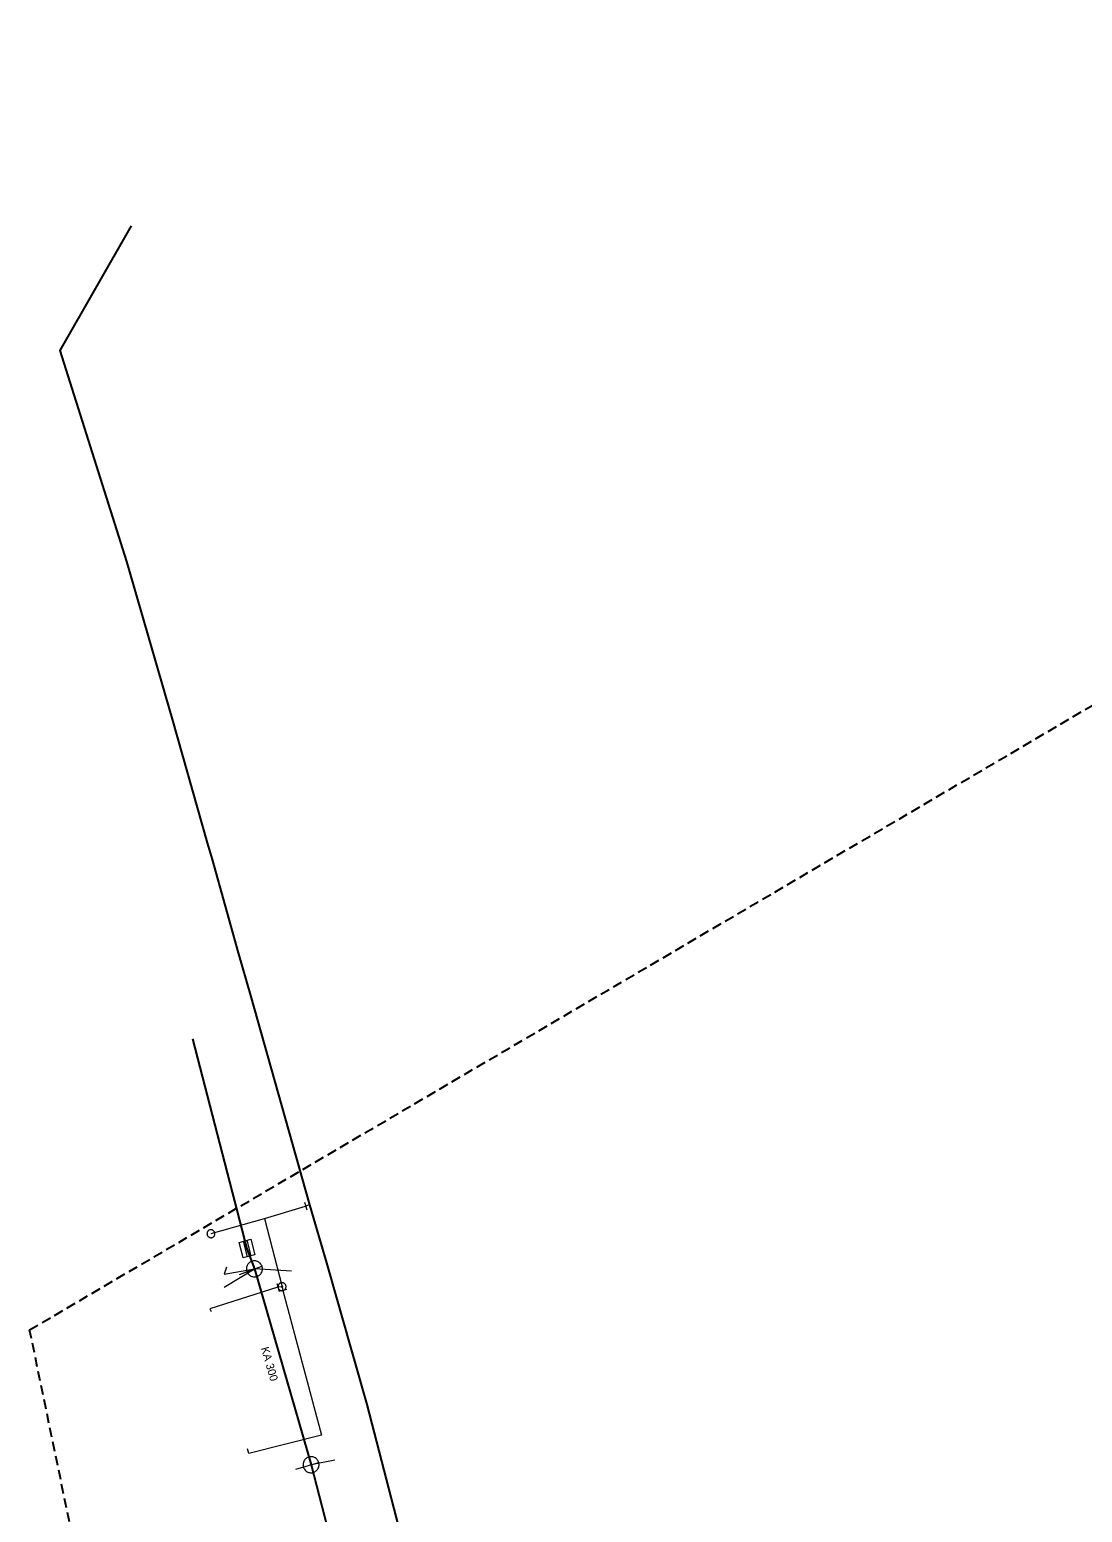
# Model space of a CAD drawing. Extents: x -807203 to -805207, y -993656 to -992505.
# Drawn here: x -807189 to -807057.5, y -992968.6 to -992783.3 of the extents above; entities that cross this region are included whole.
import ezdxf

# ---------------------------------------------------------------- set-up
doc = ezdxf.new("R2010")
doc.units = 0
doc.header["$LTSCALE"] = 0.4
doc.linetypes.add('MEDIUM_DASHED', pattern=[4.5, 3, -1.5])
for name, color, linetype, lineweight in [('1', 7, 'Continuous', 13), ('11', 7, 'Continuous', 13), ('13', 7, 'Continuous', 13), ('14', 7, 'Continuous', 25), ('17', 7, 'Continuous', 25), ('22', 7, 'Continuous', 13), ('23', 7, 'Continuous', 13), ('34', 7, 'Continuous', 13), ('47', 7, 'Continuous', 13), ('63', 7, 'MEDIUM_DASHED', 25)]:
    doc.layers.add(name, color=color, linetype=linetype, lineweight=lineweight)

msp = doc.modelspace()

# ---------------------------------------------------------------- linework, layer by layer
at = {"layer": '11'}
for p, q in [((-807164.698, -992940.463), (-807160.93, -992938.18)), ((-807156.287, -992938.489), (-807160.93, -992938.18)), ((-807150.881, -992962.09), (-807153.859, -992962.66))]:
    msp.add_line(p, q, dxfattribs=at)
msp.add_lwpolyline([(-807164.44, -992937.974), (-807164.698, -992938.833), (-807160.93, -992938.18)], dxfattribs=at)
at = {"layer": '13'}
for p, q in [((-807154.07, -992930.199), (-807154.533, -992930.34)), ((-807159.671, -992931.895), (-807157.484, -992940.411))]:
    msp.add_line(p, q, dxfattribs=at)
for points in [[(-807166.339, -992933.77), (-807159.671, -992931.895), (-807154.533, -992930.34)], [(-807157.996, -992940.48), (-807166.495, -992943.176), (-807166.358, -992943.517)], [(-807157.381, -992940.889), (-807152.535, -992958.945), (-807161.614, -992961.266), (-807161.819, -992960.686)]]:
    msp.add_lwpolyline(points, dxfattribs=at)
at = {"layer": '14'}
for p, q in [((-807168.67, -992909.44), (-807161.87, -992935.66)), ((-807161.87, -992935.66), (-807160.93, -992938.18)), ((-807160.93, -992938.18), (-807153.859, -992962.66)), ((-807153.859, -992962.66), (-807147.12, -992988.77))]:
    msp.add_line(p, q, dxfattribs=at)
at = {"layer": '14', "lineweight": 13}
for q in [(-807157.996, -992940.48), (-807157.381, -992940.889)]:
    msp.add_line((-807157.484, -992940.411), q, dxfattribs=at)
at = {"layer": '17'}
msp.add_lwpolyline([(-807176.339, -992807.832), (-807185.25, -992823.421), (-807176.901, -992849.778), (-807171.201, -992869.482), (-807166.822, -992884.952), (-807166.197, -992887.01), (-807162.951, -992898.684), (-807161.445, -992904.008), (-807154.07, -992930.199), (-807151.949, -992937.442), (-807146.899, -992955.136), (-807141.44, -992976.222)], dxfattribs=at)
at = {"layer": '22'}
for p, q in [((-807162.359, -992934.742), (-807161.857, -992936.678)), ((-807161.875, -992934.616), (-807161.373, -992936.552)), ((-807162.804, -992938.879), (-807159.993, -992937.83)), ((-807155.78, -992963.215), (-807152.898, -992962.382))]:
    msp.add_line(p, q, dxfattribs=at)
for points in [[(-807161.391, -992934.491), (-807160.889, -992936.427), (-807162.341, -992936.803), (-807162.843, -992934.868)], [(-807160.58, -992939.117), (-807160.48, -992939.073), (-807160.386, -992939.018), (-807160.297, -992938.953), (-807160.216, -992938.88), (-807160.143, -992938.798), (-807160.081, -992938.708), (-807160.028, -992938.612), (-807159.987, -992938.511), (-807159.956, -992938.405), (-807159.937, -992938.298), (-807159.93, -992938.189), (-807159.936, -992938.079), (-807159.952, -992937.971), (-807159.981, -992937.865), (-807160.021, -992937.763), (-807160.072, -992937.667), (-807160.133, -992937.575), (-807160.204, -992937.491), (-807160.284, -992937.417), (-807160.37, -992937.351), (-807160.465, -992937.294), (-807160.564, -992937.249), (-807160.669, -992937.215), (-807160.776, -992937.191), (-807160.884, -992937.181), (-807160.994, -992937.182), (-807161.103, -992937.195), (-807161.209, -992937.22), (-807161.313, -992937.256), (-807161.411, -992937.304), (-807161.504, -992937.361), (-807161.59, -992937.429), (-807161.668, -992937.505), (-807161.738, -992937.59), (-807161.797, -992937.682), (-807161.847, -992937.78), (-807161.885, -992937.883), (-807161.912, -992937.989), (-807161.927, -992938.097), (-807161.93, -992938.207), (-807161.921, -992938.316), (-807161.9, -992938.423), (-807161.867, -992938.528), (-807161.824, -992938.628), (-807161.769, -992938.723), (-807161.705, -992938.811), (-807161.631, -992938.893), (-807161.548, -992938.965), (-807161.459, -992939.028), (-807161.363, -992939.081), (-807161.262, -992939.123), (-807161.157, -992939.153), (-807161.049, -992939.173), (-807160.94, -992939.179), (-807160.831, -992939.175), (-807160.722, -992939.158), (-807160.616, -992939.129)], [(-807153.582, -992963.62), (-807153.478, -992963.584), (-807153.38, -992963.537), (-807153.286, -992963.479), (-807153.2, -992963.412), (-807153.121, -992963.336), (-807153.052, -992963.251), (-807152.992, -992963.159), (-807152.944, -992963.061), (-807152.905, -992962.959), (-807152.878, -992962.853), (-807152.862, -992962.744), (-807152.86, -992962.634), (-807152.868, -992962.525), (-807152.889, -992962.418), (-807152.921, -992962.313), (-807152.965, -992962.213), (-807153.019, -992962.117), (-807153.083, -992962.028), (-807153.157, -992961.948), (-807153.238, -992961.876), (-807153.328, -992961.812), (-807153.424, -992961.76), (-807153.525, -992961.717), (-807153.63, -992961.686), (-807153.738, -992961.667), (-807153.847, -992961.66), (-807153.957, -992961.665), (-807154.065, -992961.681), (-807154.171, -992961.71), (-807154.273, -992961.75), (-807154.37, -992961.8), (-807154.46, -992961.861), (-807154.544, -992961.931), (-807154.62, -992962.01), (-807154.686, -992962.098), (-807154.743, -992962.191), (-807154.789, -992962.291), (-807154.823, -992962.395), (-807154.847, -992962.501), (-807154.858, -992962.611), (-807154.857, -992962.72), (-807154.845, -992962.829), (-807154.82, -992962.936), (-807154.784, -992963.039), (-807154.737, -992963.138), (-807154.68, -992963.231), (-807154.612, -992963.317), (-807154.535, -992963.396), (-807154.451, -992963.465), (-807154.359, -992963.525), (-807154.262, -992963.575), (-807154.159, -992963.613), (-807154.053, -992963.641), (-807153.945, -992963.656), (-807153.836, -992963.659), (-807153.726, -992963.651), (-807153.618, -992963.63)]]:
    msp.add_lwpolyline(points, close=True, dxfattribs=at)
at = {"layer": '23'}
for points in [[(-807165.862, -992933.787), (-807165.865, -992933.734), (-807165.874, -992933.682), (-807165.889, -992933.633), (-807165.908, -992933.584), (-807165.932, -992933.538), (-807165.962, -992933.494), (-807165.995, -992933.454), (-807166.032, -992933.418), (-807166.073, -992933.385), (-807166.117, -992933.357), (-807166.164, -992933.333), (-807166.214, -992933.315), (-807166.264, -992933.302), (-807166.315, -992933.295), (-807166.367, -992933.292), (-807166.421, -992933.296), (-807166.471, -992933.304), (-807166.523, -992933.319), (-807166.57, -992933.337), (-807166.617, -992933.361), (-807166.661, -992933.392), (-807166.701, -992933.425), (-807166.738, -992933.463), (-807166.771, -992933.503), (-807166.798, -992933.547), (-807166.821, -992933.595), (-807166.839, -992933.643), (-807166.852, -992933.694), (-807166.859, -992933.746), (-807166.862, -992933.798), (-807166.859, -992933.85), (-807166.85, -992933.902), (-807166.836, -992933.953), (-807166.817, -992934.001), (-807166.792, -992934.046), (-807166.763, -992934.09), (-807166.73, -992934.131), (-807166.692, -992934.168), (-807166.651, -992934.2)], [(-807166.523, -992933.319), (-807166.57, -992933.337), (-807166.617, -992933.361), (-807166.661, -992933.392), (-807166.701, -992933.425), (-807166.738, -992933.463), (-807166.771, -992933.503), (-807166.798, -992933.547), (-807166.821, -992933.595), (-807166.839, -992933.643), (-807166.852, -992933.694), (-807166.859, -992933.746), (-807166.862, -992933.798), (-807166.859, -992933.85), (-807166.85, -992933.902), (-807166.836, -992933.953), (-807166.817, -992934.001), (-807166.792, -992934.046), (-807166.763, -992934.09), (-807166.73, -992934.131), (-807166.692, -992934.168), (-807166.651, -992934.2), (-807166.608, -992934.228), (-807166.56, -992934.251), (-807166.512, -992934.27), (-807166.46, -992934.282), (-807166.409, -992934.289), (-807166.357, -992934.292), (-807166.305, -992934.288), (-807166.253, -992934.28), (-807166.202, -992934.266), (-807166.154, -992934.246), (-807166.107, -992934.222), (-807166.064, -992934.194), (-807166.024, -992934.159), (-807165.987, -992934.123), (-807165.955, -992934.082), (-807165.926, -992934.037), (-807165.903, -992933.99), (-807165.885, -992933.941)], [(-807166.651, -992934.2), (-807166.608, -992934.228), (-807166.56, -992934.251), (-807166.512, -992934.27), (-807166.46, -992934.282), (-807166.409, -992934.289), (-807166.357, -992934.292), (-807166.305, -992934.288), (-807166.253, -992934.28), (-807166.202, -992934.266), (-807166.154, -992934.246), (-807166.107, -992934.222), (-807166.064, -992934.194), (-807166.024, -992934.159), (-807165.987, -992934.123), (-807165.955, -992934.082), (-807165.926, -992934.037), (-807165.903, -992933.99), (-807165.885, -992933.941), (-807165.873, -992933.89), (-807165.865, -992933.839), (-807165.862, -992933.787), (-807165.865, -992933.734), (-807165.874, -992933.682), (-807165.889, -992933.633), (-807165.908, -992933.584), (-807165.932, -992933.538), (-807165.962, -992933.494), (-807165.995, -992933.454), (-807166.032, -992933.418), (-807166.073, -992933.385), (-807166.117, -992933.357), (-807166.164, -992933.333), (-807166.214, -992933.315), (-807166.264, -992933.302), (-807166.315, -992933.295), (-807166.367, -992933.292), (-807166.421, -992933.296), (-807166.471, -992933.304), (-807166.523, -992933.319)], [(-807165.885, -992933.941), (-807165.873, -992933.89), (-807165.865, -992933.839), (-807165.862, -992933.787)]]:
    msp.add_lwpolyline(points, dxfattribs=at)
at = {"layer": '34'}
for p, q in [((-807154.678, -992929.861), (-807154.388, -992930.818)), ((-807158.136, -992940), (-807157.856, -992940.96)), ((-807156.896, -992940.765), (-807157.865, -992941.011))]:
    msp.add_line(p, q, dxfattribs=at)
at = {"layer": '47'}
for points in [[(-807157.359, -992940.895), (-807157.31, -992940.879), (-807157.261, -992940.858), (-807157.216, -992940.832), (-807157.173, -992940.803), (-807157.134, -992940.768), (-807157.098, -992940.729), (-807157.068, -992940.687), (-807157.041, -992940.642), (-807157.019, -992940.595), (-807157.002, -992940.545), (-807156.99, -992940.493), (-807156.985, -992940.442), (-807156.984, -992940.39), (-807156.989, -992940.337), (-807156.999, -992940.286), (-807157.015, -992940.237), (-807157.036, -992940.188), (-807157.062, -992940.142), (-807157.091, -992940.1), (-807157.126, -992940.061), (-807157.165, -992940.025), (-807157.207, -992939.994), (-807157.252, -992939.967), (-807157.299, -992939.945), (-807157.349, -992939.929), (-807157.401, -992939.917), (-807157.453, -992939.911), (-807157.504, -992939.911), (-807157.557, -992939.916), (-807157.608, -992939.926), (-807157.657, -992939.942), (-807157.706, -992939.963), (-807157.752, -992939.988), (-807157.794, -992940.018), (-807157.833, -992940.053), (-807157.869, -992940.091), (-807157.9, -992940.133), (-807157.927, -992940.179), (-807157.949, -992940.226), (-807157.965, -992940.276), (-807157.977, -992940.328), (-807157.983, -992940.379), (-807157.983, -992940.431), (-807157.978, -992940.484), (-807157.968, -992940.535), (-807157.952, -992940.584), (-807157.931, -992940.633), (-807157.906, -992940.678), (-807157.876, -992940.721), (-807157.841, -992940.76), (-807157.803, -992940.796), (-807157.761, -992940.827), (-807157.716, -992940.853), (-807157.668, -992940.875), (-807157.618, -992940.892), (-807157.566, -992940.904), (-807157.516, -992940.909), (-807157.463, -992940.91), (-807157.41, -992940.905)], [(-807157.463, -992940.49), (-807157.454, -992940.488), (-807157.447, -992940.484), (-807157.44, -992940.48), (-807157.433, -992940.475), (-807157.426, -992940.469), (-807157.421, -992940.462), (-807157.415, -992940.456), (-807157.411, -992940.449), (-807157.408, -992940.441), (-807157.405, -992940.433), (-807157.403, -992940.424), (-807157.402, -992940.415), (-807157.402, -992940.407), (-807157.402, -992940.399), (-807157.404, -992940.39), (-807157.406, -992940.381), (-807157.41, -992940.374), (-807157.414, -992940.367), (-807157.419, -992940.36), (-807157.425, -992940.353), (-807157.432, -992940.348), (-807157.438, -992940.342), (-807157.445, -992940.338), (-807157.454, -992940.334), (-807157.461, -992940.332), (-807157.47, -992940.33), (-807157.479, -992940.329), (-807157.487, -992940.329), (-807157.495, -992940.329), (-807157.504, -992940.331), (-807157.513, -992940.333), (-807157.52, -992940.337), (-807157.527, -992940.341), (-807157.534, -992940.346), (-807157.541, -992940.352), (-807157.547, -992940.358), (-807157.552, -992940.365), (-807157.556, -992940.372), (-807157.56, -992940.381), (-807157.562, -992940.388), (-807157.564, -992940.397), (-807157.565, -992940.406), (-807157.565, -992940.414), (-807157.565, -992940.422), (-807157.563, -992940.431), (-807157.561, -992940.44), (-807157.557, -992940.447), (-807157.553, -992940.454), (-807157.548, -992940.461), (-807157.542, -992940.468), (-807157.536, -992940.474), (-807157.529, -992940.479), (-807157.522, -992940.483), (-807157.514, -992940.486), (-807157.506, -992940.489), (-807157.497, -992940.491), (-807157.488, -992940.492), (-807157.48, -992940.492), (-807157.472, -992940.492)]]:
    msp.add_lwpolyline(points, close=True, dxfattribs=at)
at = {"layer": '63'}
msp.add_lwpolyline([(-807189.02, -992945.815), (-806576.348, -992585.749), (-806576.348, -992585.749), (-805244.939, -992598.309), (-805244.939, -992598.309), (-805207.257, -992947.211), (-805207.257, -992947.211), (-805210.049, -993545.926), (-805210.049, -993545.926), (-805797.599, -993596.168), (-805797.599, -993596.168), (-807062.019, -993558.487), (-807062.019, -993558.487)], close=True, dxfattribs=at)

# ---------------------------------------------------------------- texts
at = {"layer": '1'}
msp.add_text('KA 300', height=1, rotation=286, dxfattribs=at).set_placement((-807160.134, -992948.088))

doc.saveas('drawing.dxf')
